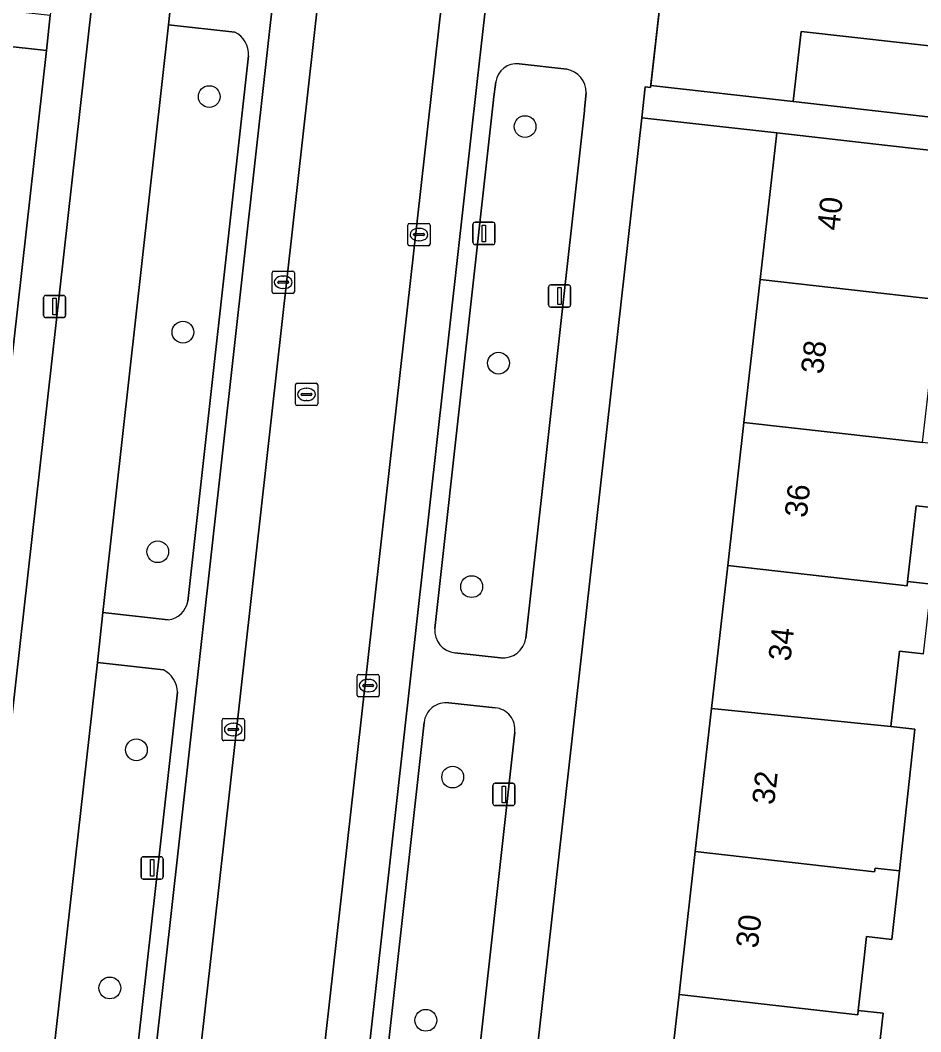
# Model space of a CAD drawing. Extents: x 162026 to 163502, y 387295 to 388169.
# Drawn here: x 162271.99 to 162312.4, y 387747.09 to 387792.48 of the extents above; entities that cross this region are included whole.
import ezdxf

# ---------------------------------------------------------------- set-up
doc = ezdxf.new("R2010")
doc.units = 0
for name, color, linetype in [('IMGEO_Berm_groen', 7, 'Continuous'), ('IMGEO_Boom', 7, 'Continuous'), ('IMGEO_Erf', 7, 'Continuous'), ('IMGEO_Fietspad_gesloten', 7, 'Continuous'), ('IMGEO_Groenvoorziening', 7, 'Continuous'), ('IMGEO_Kolk', 7, 'Continuous'), ('IMGEO_Lichtmast', 7, 'Continuous'), ('IMGEO_Muur', 7, 'Continuous'), ('IMGEO_Pand', 7, 'Continuous'), ('IMGEO_Pand_nummerreeks', 7, 'Continuous'), ('IMGEO_Parkeervlak_open', 7, 'Continuous'), ('IMGEO_Rijbaan_lokaal_gesloten', 7, 'Continuous'), ('IMGEO_Rioolput', 7, 'Continuous'), ('IMGEO_Voetpad_open', 7, 'Continuous')]:
    doc.layers.add(name, color=color, linetype=linetype)

msp = doc.modelspace()

# ---------------------------------------------------------------- linework, layer by layer
at = {"layer": 'IMGEO_Berm_groen'}
for points in [[(162281.616, 387791.948), (162278.652, 387792.276), (162275.701, 387765.902), (162278.634, 387765.568)], [(162279.508, 387766.397), (162282.229, 387790.883)], [(162278.414, 387763.326), (162275.454, 387763.658), (162272.106, 387733.912), (162274.927, 387733.596)], [(162275.919, 387734.426), (162279.054, 387762.323)]]:
    msp.add_lwpolyline(points, dxfattribs=at)
for centre, radius, start, end in [((162281.14, 387790.965), 1.092, 355.6719, 64.1764), ((162278.505, 387766.579), 1.019, 277.2498, 349.7229), ((162277.921, 387762.306), 1.133, 0.865, 64.2178)]:
    msp.add_arc(centre, radius, start, end, dxfattribs=at)
at = {"layer": 'IMGEO_Boom'}
for centre in [(162280.473, 387789.054), (162294.643, 387787.708), (162279.293, 387778.481), (162293.45, 387777.094), (162278.163, 387768.63), (162292.248, 387767.063), (162277.204, 387759.741), (162291.396, 387758.518), (162276.01, 387749.054), (162290.189, 387747.603)]:
    msp.add_circle(centre, 0.489, dxfattribs=at)
at = {"layer": 'IMGEO_Erf'}
for points in [[(162360.929, 387806.153), (162306.963, 387812.388), (162304.731, 387812.656), (162302.745, 387811.357), (162302.135, 387805.96), (162300.281, 387789.552), (162306.672, 387788.828), (162307.029, 387791.981), (162313.859, 387791.208)], [(162313.317, 387770.569), (162312.194, 387770.696), (162311.809, 387767.301), (162312.879, 387767.18)], [(162312.523, 387764.042), (162311.441, 387764.164), (162311.058, 387760.783), (162312.139, 387760.661), (162311.441, 387754.307), (162311.093, 387751.233), (162309.97, 387751.36), (162309.816, 387750), (162309.594, 387748.046), (162310.706, 387747.921), (162310.348, 387744.766)]]:
    msp.add_lwpolyline(points, dxfattribs=at)
for points in [[(162273.165, 387791.126), (162267.189, 387791.787), (162266.468, 387785.258), (162265.764, 387778.887), (162265.064, 387772.546), (162264.36, 387766.174), (162263.657, 387759.813), (162262.943, 387753.352), (162262.573, 387750), (162262.226, 387746.862), (162261.527, 387740.53), (162260.823, 387734.159), (162260.125, 387727.838), (162259.419, 387721.447), (162258.717, 387715.095), (162257.997, 387708.577), (162257.287, 387708.655), (162257.121, 387707.155), (162258.204, 387707.032), (162263.701, 387706.408), (162268.384, 387748.57)], [(162301.695, 387750), (162302.282, 387755.18), (162303.009, 387761.598), (162303.736, 387768.016), (162304.463, 387774.434), (162305.191, 387780.852), (162305.935, 387787.422), (162299.876, 387788.101), (162295.696, 387750.809), (162291.817, 387716.197), (162290.503, 387704.362), (162296.448, 387703.689), (162297.192, 387710.254), (162297.919, 387716.672), (162298.646, 387723.09), (162299.373, 387729.508), (162300.1, 387735.926), (162300.828, 387742.344), (162301.555, 387748.762)]]:
    msp.add_lwpolyline(points, close=True, dxfattribs=at)
at = {"layer": 'IMGEO_Fietspad_gesloten'}
for points in [[(162288.097, 387908.488), (162278.956, 387826.545), (162278.87, 387825.665), (162278.372, 387825.72), (162277.589, 387818.699), (162278.067, 387818.669), (162270.183, 387748.502), (162261.381, 387669.505)], [(162272.106, 387733.912), (162275.454, 387763.658), (162275.701, 387765.902), (162278.652, 387792.276), (162278.879, 387794.52), (162280.59, 387809.842), (162281.546, 387818.246), (162282.058, 387818.211), (162282.843, 387825.189), (162282.325, 387825.242), (162283.687, 387837.34), (162286.582, 387863.057), (162286.832, 387865.282)]]:
    msp.add_lwpolyline(points, dxfattribs=at)
at = {"layer": 'IMGEO_Groenvoorziening'}
for points in [[(162296.511, 387790.278), (162294.372, 387790.52)], [(162293.326, 387789.719), (162293.224, 387788.934), (162293.22, 387788.901), (162290.6, 387765.183)], [(162297.317, 387788.491), (162297.385, 387789.226)], [(162294.678, 387764.747), (162297.308, 387788.408), (162297.317, 387788.491)], [(162291.488, 387764.093), (162293.544, 387763.874)], [(162293.308, 387761.627), (162291.221, 387761.847)], [(162290.111, 387760.971), (162287.029, 387733.23)], [(162291.103, 387732.722), (162294.178, 387760.535)]]:
    msp.add_lwpolyline(points, dxfattribs=at)
for centre, radius, start, end in [((162294.258, 387789.586), 0.941, 83.025, 171.8629), ((162296.332, 387789.24), 1.053, 359.2191, 80.2204), ((162291.593, 387765.085), 0.998, 174.3766, 263.9614), ((162293.658, 387764.899), 1.031, 263.6367, 351.5444), ((162291.096, 387760.865), 0.99, 82.7249, 173.8353), ((162293.218, 387760.663), 0.968, 352.4014, 84.6875)]:
    msp.add_arc(centre, radius, start, end, dxfattribs=at)
at = {"layer": 'IMGEO_Kolk'}
for p, q in [((162289.458, 387783.362), (162290.31, 387783.362)), ((162289.383, 387782.436), (162289.383, 387783.288)), ((162289.685, 387782.905), (162290.083, 387782.905)), ((162289.871, 387783.142), (162289.896, 387783.142)), ((162290.384, 387783.288), (162290.384, 387782.436)), ((162289.642, 387782.856), (162289.642, 387782.868)), ((162290.08, 387782.819), (162289.682, 387782.819)), ((162289.894, 387782.582), (162289.869, 387782.582)), ((162290.126, 387782.868), (162290.126, 387782.856)), ((162290.31, 387782.362), (162289.458, 387782.362)), ((162283.293, 387780.296), (162283.293, 387781.148)), ((162283.368, 387781.222), (162284.22, 387781.222)), ((162284.294, 387781.148), (162284.294, 387780.296)), ((162283.552, 387780.716), (162283.552, 387780.728)), ((162283.99, 387780.679), (162283.592, 387780.679)), ((162283.595, 387780.765), (162283.993, 387780.765)), ((162283.781, 387781.002), (162283.806, 387781.002)), ((162284.036, 387780.728), (162284.036, 387780.716)), ((162284.22, 387780.222), (162283.368, 387780.222)), ((162283.804, 387780.442), (162283.779, 387780.442)), ((162287.103, 387762.197), (162287.103, 387763.049)), ((162287.178, 387763.123), (162288.03, 387763.123)), ((162288.104, 387763.049), (162288.104, 387762.197)), ((162287.362, 387762.617), (162287.362, 387762.629)), ((162287.8, 387762.58), (162287.402, 387762.58)), ((162287.405, 387762.666), (162287.803, 387762.666)), ((162287.591, 387762.903), (162287.616, 387762.903)), ((162287.846, 387762.629), (162287.846, 387762.617)), ((162288.03, 387762.123), (162287.178, 387762.123)), ((162287.614, 387762.343), (162287.589, 387762.343)), ((162281.126, 387761.152), (162281.978, 387761.152)), ((162281.051, 387760.226), (162281.051, 387761.078)), ((162281.31, 387760.646), (162281.31, 387760.658)), ((162281.353, 387760.695), (162281.751, 387760.695)), ((162281.539, 387760.932), (162281.564, 387760.932)), ((162281.794, 387760.658), (162281.794, 387760.646)), ((162282.052, 387761.078), (162282.052, 387760.226)), ((162281.748, 387760.609), (162281.35, 387760.609)), ((162281.562, 387760.372), (162281.537, 387760.372)), ((162281.978, 387760.152), (162281.126, 387760.152))]:
    msp.add_line(p, q, dxfattribs=at)
for points in [[(162289.458, 387783.362), (162290.31, 387783.362)], [(162289.383, 387782.436), (162289.383, 387783.288)], [(162290.384, 387783.288), (162290.384, 387782.436)], [(162290.31, 387782.362), (162289.458, 387782.362)], [(162283.293, 387780.296), (162283.293, 387781.148)], [(162283.368, 387781.222), (162284.22, 387781.222)], [(162284.294, 387781.148), (162284.294, 387780.296)], [(162284.22, 387780.222), (162283.368, 387780.222)], [(162287.103, 387762.197), (162287.103, 387763.049)], [(162287.178, 387763.123), (162288.03, 387763.123)], [(162288.104, 387763.049), (162288.104, 387762.197)], [(162288.03, 387762.123), (162287.178, 387762.123)], [(162281.126, 387761.152), (162281.978, 387761.152)], [(162281.051, 387760.226), (162281.051, 387761.078)], [(162282.052, 387761.078), (162282.052, 387760.226)], [(162281.978, 387760.152), (162281.126, 387760.152)]]:
    msp.add_lwpolyline(points, dxfattribs=at)
for centre, radius, start, end in [((162289.46, 387783.286), 0.0765, 91.552, 178.448), ((162289.46, 387783.286), 0.0765, 91.552, 178.448), ((162290.308, 387783.286), 0.0765, 1.552, 88.448), ((162290.308, 387783.286), 0.0765, 1.552, 88.448), ((162289.682, 387782.865), 0.0403, 85.8775, 175.7526), ((162290.087, 387782.867), 0.0386, 1.7309, 96.639), ((162289.679, 387782.855), 0.0366, 178.938, 274.7102), ((162290.083, 387782.862), 0.043, 264.8664, 352.4533), ((162289.46, 387782.438), 0.0765, 181.552, 268.448), ((162289.46, 387782.438), 0.0765, 181.552, 268.448), ((162290.308, 387782.438), 0.0765, 271.552, 358.448), ((162290.308, 387782.438), 0.0765, 271.552, 358.448), ((162283.37, 387781.146), 0.0765, 91.552, 178.448), ((162283.37, 387781.146), 0.0765, 91.552, 178.448), ((162284.218, 387781.146), 0.0765, 1.552, 88.448), ((162284.218, 387781.146), 0.0765, 1.552, 88.448), ((162283.592, 387780.725), 0.0403, 85.8775, 175.7526), ((162283.589, 387780.715), 0.0366, 178.938, 274.7102), ((162283.993, 387780.722), 0.043, 264.8664, 352.4533), ((162283.997, 387780.727), 0.0386, 1.7309, 96.639), ((162283.37, 387780.298), 0.0765, 181.552, 268.448), ((162283.37, 387780.298), 0.0765, 181.552, 268.448), ((162284.218, 387780.298), 0.0765, 271.552, 358.448), ((162284.218, 387780.298), 0.0765, 271.552, 358.448), ((162287.18, 387763.047), 0.0765, 91.552, 178.448), ((162287.18, 387763.047), 0.0765, 91.552, 178.448), ((162288.028, 387763.047), 0.0765, 1.552, 88.448), ((162288.028, 387763.047), 0.0765, 1.552, 88.448), ((162287.402, 387762.626), 0.0403, 85.8775, 175.7526), ((162287.399, 387762.616), 0.0366, 178.938, 274.7102), ((162287.803, 387762.623), 0.043, 264.8664, 352.4533), ((162287.807, 387762.628), 0.0386, 1.7309, 96.639), ((162287.18, 387762.199), 0.0765, 181.552, 268.448), ((162287.18, 387762.199), 0.0765, 181.552, 268.448), ((162288.028, 387762.199), 0.0765, 271.552, 358.448), ((162288.028, 387762.199), 0.0765, 271.552, 358.448), ((162281.128, 387761.076), 0.0765, 91.552, 178.448), ((162281.128, 387761.076), 0.0765, 91.552, 178.448), ((162281.976, 387761.076), 0.0765, 1.552, 88.448), ((162281.976, 387761.076), 0.0765, 1.552, 88.448), ((162281.35, 387760.655), 0.0403, 85.8775, 175.7526), ((162281.755, 387760.657), 0.0386, 1.7309, 96.639), ((162281.128, 387760.228), 0.0765, 181.552, 268.448), ((162281.128, 387760.228), 0.0765, 181.552, 268.448), ((162281.347, 387760.645), 0.0366, 178.938, 274.7102), ((162281.751, 387760.652), 0.043, 264.8664, 352.4533), ((162281.976, 387760.228), 0.0765, 271.552, 358.448), ((162281.976, 387760.228), 0.0765, 271.552, 358.448)]:
    msp.add_arc(centre, radius, start, end, dxfattribs=at)
for centre, major_axis, ratio, start_param, end_param in [((162289.87, 387782.862), (-0.387, 0.002), 0.722429, 4.712389, 7.853982), ((162289.895, 387782.862), (-0.39, 0.002), 0.717154, 1.570796, 4.712389), ((162283.78, 387780.722), (-0.387, 0.002), 0.722429, 4.712389, 7.853982), ((162283.805, 387780.722), (-0.39, 0.002), 0.717154, 1.570796, 4.712389), ((162287.59, 387762.623), (-0.387, 0.002), 0.722429, 4.712389, 7.853982), ((162287.615, 387762.623), (-0.39, 0.002), 0.717154, 1.570796, 4.712389), ((162281.538, 387760.652), (-0.387, 0.002), 0.722429, 4.712389, 7.853982), ((162281.563, 387760.652), (-0.39, 0.002), 0.717154, 1.570796, 4.712389)]:
    msp.add_ellipse(centre, major_axis=major_axis, ratio=ratio, start_param=start_param, end_param=end_param, dxfattribs=at)
at = {"layer": 'IMGEO_Lichtmast'}
for p, q in [((162292.404, 387783.414), (162293.194, 387783.414)), ((162293.194, 387783.414), (162292.404, 387783.414)), ((162292.304, 387782.514), (162292.304, 387783.314)), ((162292.304, 387783.314), (162292.304, 387782.514)), ((162293.294, 387783.314), (162293.294, 387782.514)), ((162293.294, 387782.514), (162293.294, 387783.314)), ((162293.194, 387782.414), (162292.404, 387782.414)), ((162292.404, 387782.414), (162293.194, 387782.414)), ((162295.696, 387779.705), (162295.696, 387780.505)), ((162295.696, 387780.505), (162295.696, 387779.705)), ((162295.796, 387780.605), (162296.586, 387780.605)), ((162296.586, 387780.605), (162295.796, 387780.605)), ((162296.686, 387780.505), (162296.686, 387779.705)), ((162296.686, 387779.705), (162296.686, 387780.505)), ((162273.038, 387779.234), (162273.038, 387780.034)), ((162273.038, 387780.034), (162273.038, 387779.234)), ((162273.138, 387780.134), (162273.928, 387780.134)), ((162273.928, 387780.134), (162273.138, 387780.134)), ((162274.028, 387780.034), (162274.028, 387779.234)), ((162274.028, 387779.234), (162274.028, 387780.034)), ((162296.586, 387779.605), (162295.796, 387779.605)), ((162295.796, 387779.605), (162296.586, 387779.605)), ((162273.928, 387779.134), (162273.138, 387779.134)), ((162273.138, 387779.134), (162273.928, 387779.134)), ((162293.201, 387757.338), (162293.201, 387758.138)), ((162293.201, 387758.138), (162293.201, 387757.338)), ((162293.301, 387758.238), (162294.091, 387758.238)), ((162294.091, 387758.238), (162293.301, 387758.238)), ((162294.191, 387758.138), (162294.191, 387757.338)), ((162294.191, 387757.338), (162294.191, 387758.138)), ((162294.091, 387757.238), (162293.301, 387757.238)), ((162293.301, 387757.238), (162294.091, 387757.238)), ((162277.414, 387754.042), (162277.414, 387754.842)), ((162277.414, 387754.842), (162277.414, 387754.042)), ((162277.514, 387754.942), (162278.304, 387754.942)), ((162278.304, 387754.942), (162277.514, 387754.942)), ((162278.404, 387754.842), (162278.404, 387754.042)), ((162278.404, 387754.042), (162278.404, 387754.842)), ((162278.304, 387753.942), (162277.514, 387753.942)), ((162277.514, 387753.942), (162278.304, 387753.942))]:
    msp.add_line(p, q, dxfattribs=at)
for points in [[(162292.724, 387783.289), (162292.874, 387783.289), (162292.874, 387782.539), (162292.724, 387782.539), (162292.724, 387783.289)], [(162296.116, 387780.48), (162296.266, 387780.48), (162296.266, 387779.73), (162296.116, 387779.73), (162296.116, 387780.48)], [(162273.458, 387780.009), (162273.608, 387780.009), (162273.608, 387779.259), (162273.458, 387779.259), (162273.458, 387780.009)], [(162293.621, 387758.113), (162293.771, 387758.113), (162293.771, 387757.363), (162293.621, 387757.363), (162293.621, 387758.113)], [(162277.834, 387754.817), (162277.984, 387754.817), (162277.984, 387754.067), (162277.834, 387754.067), (162277.834, 387754.817)]]:
    msp.add_lwpolyline(points, dxfattribs=at)
for centre, start, end in [((162292.404, 387783.314), 90, 180), ((162292.404, 387783.314), 90, 180), ((162293.194, 387783.314), 0, 90), ((162293.194, 387783.314), 360, 90), ((162292.404, 387782.514), 180, 270), ((162292.404, 387782.514), 180, 270), ((162293.194, 387782.514), 270, 0), ((162293.194, 387782.514), 270, 0), ((162295.796, 387780.505), 90, 180), ((162295.796, 387780.505), 90, 180), ((162296.586, 387780.505), 0, 90), ((162296.586, 387780.505), 360, 90), ((162273.138, 387780.034), 90, 180), ((162273.138, 387780.034), 90, 180), ((162273.928, 387780.034), 0, 90), ((162273.928, 387780.034), 360, 90), ((162295.796, 387779.705), 180, 270), ((162295.796, 387779.705), 180, 270), ((162296.586, 387779.705), 270, 0), ((162296.586, 387779.705), 270, 0), ((162273.138, 387779.234), 180, 270), ((162273.138, 387779.234), 180, 270), ((162273.928, 387779.234), 270, 0), ((162273.928, 387779.234), 270, 0), ((162293.301, 387758.138), 90, 180), ((162293.301, 387758.138), 90, 180), ((162294.091, 387758.138), 0, 90), ((162294.091, 387758.138), 360, 90), ((162293.301, 387757.338), 180, 270), ((162293.301, 387757.338), 180, 270), ((162294.091, 387757.338), 270, 0), ((162294.091, 387757.338), 270, 0), ((162277.514, 387754.842), 90, 180), ((162277.514, 387754.842), 90, 180), ((162278.304, 387754.842), 0, 90), ((162278.304, 387754.842), 360, 90), ((162277.514, 387754.042), 180, 270), ((162277.514, 387754.042), 180, 270), ((162278.304, 387754.042), 270, 0), ((162278.304, 387754.042), 270, 0)]:
    msp.add_arc(centre, 0.1, start, end, dxfattribs=at)
at = {"layer": 'IMGEO_Muur'}
msp.add_lwpolyline([(162300.27, 387789.459), (162302.135, 387805.96)], dxfattribs=at)
at = {"layer": 'IMGEO_Pand'}
for points in [[(162313.859, 387791.208), (162307.029, 387791.981), (162306.672, 387788.828), (162313.502, 387788.054)], [(162313.259, 387779.939), (162313.285, 387780.167), (162313.666, 387783.538), (162314.692, 387783.422), (162315.029, 387786.391), (162310.904, 387786.859), (162305.935, 387787.422), (162305.191, 387780.852)], [(162305.191, 387780.852), (162304.463, 387774.434), (162312.475, 387773.527), (162312.873, 387777.035), (162314.026, 387776.904), (162314.382, 387780.043), (162313.285, 387780.167), (162313.259, 387779.939)], [(162311.787, 387767.105), (162311.809, 387767.301), (162312.194, 387770.696), (162313.317, 387770.569), (162313.636, 387773.384), (162312.475, 387773.527), (162304.463, 387774.434), (162303.736, 387768.016)], [(162303.736, 387768.016), (162303.009, 387761.598), (162311.058, 387760.783), (162311.441, 387764.164), (162312.523, 387764.042), (162312.879, 387767.18), (162311.809, 387767.301), (162311.787, 387767.105)], [(162312.139, 387760.661), (162311.058, 387760.783), (162303.009, 387761.598), (162302.282, 387755.18), (162310.329, 387754.269), (162310.347, 387754.431), (162311.441, 387754.307)], [(162309.572, 387747.854), (162309.594, 387748.046), (162309.816, 387750), (162309.97, 387751.36), (162311.093, 387751.233), (162311.441, 387754.307), (162310.347, 387754.431), (162310.329, 387754.269), (162302.282, 387755.18), (162301.695, 387750), (162301.555, 387748.762)], [(162301.555, 387748.762), (162300.828, 387742.344), (162308.92, 387741.428), (162309.984, 387741.4), (162311.513, 387741.226), (162311.895, 387744.592), (162310.348, 387744.766), (162310.706, 387747.921), (162309.594, 387748.046), (162309.572, 387747.854)]]:
    msp.add_lwpolyline(points, close=True, dxfattribs=at)
at = {"layer": 'IMGEO_Parkeervlak_open'}
for points in [[(162280.695, 387751.699), (162287.006, 387808.114)], [(162284.902, 387807.407), (162278.703, 387751.857), (162273.411, 387704.935), (162275.389, 387704.712), (162277.051, 387719.431), (162280.695, 387751.699)], [(162292.493, 387807.458), (162285.406, 387744.3), (162281.03, 387705.382)], [(162283.154, 387706.135), (162287.384, 387743.942), (162292.495, 387789.737), (162292.997, 387794.228), (162294.36, 387806.319)]]:
    msp.add_lwpolyline(points, dxfattribs=at)
at = {"layer": 'IMGEO_Rijbaan_lokaal_gesloten'}
for points in [[(162293.541, 387866.933), (162293.019, 387862.21), (162290.172, 387836.436), (162289.313, 387828.914), (162289.192, 387827.743), (162287.762, 387814.78), (162287.006, 387808.114), (162280.695, 387751.699), (162277.051, 387719.431)], [(162285.406, 387744.3), (162292.493, 387807.458), (162292.904, 387811.196), (162294.998, 387829.811), (162295.007, 387829.89), (162295.154, 387831.121), (162295.688, 387835.856), (162298.53, 387861.44), (162299.054, 387866.158)]]:
    msp.add_lwpolyline(points, dxfattribs=at)
at = {"layer": 'IMGEO_Rioolput'}
for p, q in [((162284.339, 387775.263), (162284.339, 387776.115)), ((162284.414, 387776.189), (162285.266, 387776.189)), ((162285.34, 387776.115), (162285.34, 387775.263)), ((162284.598, 387775.683), (162284.598, 387775.695)), ((162285.036, 387775.646), (162284.638, 387775.646)), ((162284.641, 387775.732), (162285.039, 387775.732)), ((162284.827, 387775.969), (162284.852, 387775.969)), ((162285.082, 387775.695), (162285.082, 387775.683)), ((162285.266, 387775.189), (162284.414, 387775.189)), ((162284.85, 387775.409), (162284.825, 387775.409))]:
    msp.add_line(p, q, dxfattribs=at)
for points in [[(162284.339, 387775.263), (162284.339, 387776.115)], [(162284.414, 387776.189), (162285.266, 387776.189)], [(162285.34, 387776.115), (162285.34, 387775.263)], [(162285.266, 387775.189), (162284.414, 387775.189)]]:
    msp.add_lwpolyline(points, dxfattribs=at)
for centre, radius, start, end in [((162284.416, 387776.113), 0.0765, 91.552, 178.448), ((162284.416, 387776.113), 0.0765, 91.552, 178.448), ((162285.264, 387776.113), 0.0765, 1.552, 88.448), ((162285.264, 387776.113), 0.0765, 1.552, 88.448), ((162284.638, 387775.692), 0.0403, 85.8775, 175.7526), ((162284.635, 387775.682), 0.0366, 178.938, 274.7102), ((162285.039, 387775.689), 0.043, 264.8664, 352.4533), ((162285.043, 387775.694), 0.0386, 1.7309, 96.639), ((162284.416, 387775.265), 0.0765, 181.552, 268.448), ((162284.416, 387775.265), 0.0765, 181.552, 268.448), ((162285.264, 387775.265), 0.0765, 271.552, 358.448), ((162285.264, 387775.265), 0.0765, 271.552, 358.448)]:
    msp.add_arc(centre, radius, start, end, dxfattribs=at)
for centre, major_axis, ratio, start_param, end_param in [((162284.826, 387775.689), (-0.387, 0.002), 0.722429, 4.712389, 7.853982), ((162284.851, 387775.689), (-0.39, 0.002), 0.717154, 1.570796, 4.712389)]:
    msp.add_ellipse(centre, major_axis=major_axis, ratio=ratio, start_param=start_param, end_param=end_param, dxfattribs=at)
at = {"layer": 'IMGEO_Voetpad_open'}
for points in [[(162278.638, 387840.188), (162277.973, 387834.139), (162277.255, 387827.421), (162277.144, 387825.832), (162276.387, 387818.853), (162275.948, 387815.9), (162273.341, 387792.696), (162273.165, 387791.126), (162268.384, 387748.57), (162263.701, 387706.408), (162263.602, 387705.513), (162260.688, 387679.28), (162259.835, 387671.845), (162259.358, 387667.311)], [(162258.548, 387665.971), (162258.434, 387664.862), (162260.283, 387664.663), (162260.87, 387664.615), (162261.381, 387669.505), (162270.183, 387748.502), (162278.067, 387818.669), (162277.589, 387818.699), (162278.372, 387825.72)], [(162290.361, 387703.086), (162290.503, 387704.362), (162291.817, 387716.197), (162295.696, 387750.809), (162299.876, 387788.101), (162300.031, 387789.486), (162300.27, 387789.459), (162300.281, 387789.552), (162302.135, 387805.96), (162302.745, 387811.357), (162303.178, 387815.842), (162302.483, 387815.921), (162299.685, 387816.236)], [(162273.411, 387704.935), (162278.703, 387751.857), (162284.902, 387807.407)], [(162294.36, 387806.319), (162292.997, 387794.228), (162292.495, 387789.737), (162287.384, 387743.942), (162283.154, 387706.135)], [(162281.83, 387794.192), (162278.879, 387794.52), (162278.652, 387792.276), (162281.616, 387791.948)], [(162282.229, 387790.883), (162279.508, 387766.397)], [(162294.372, 387790.52), (162296.511, 387790.278)], [(162290.6, 387765.183), (162293.22, 387788.901), (162293.224, 387788.934), (162293.326, 387789.719)], [(162313.502, 387788.054), (162306.672, 387788.828), (162300.281, 387789.552), (162300.27, 387789.459), (162300.031, 387789.486), (162299.876, 387788.101), (162305.935, 387787.422), (162310.904, 387786.859), (162315.029, 387786.391)], [(162297.385, 387789.226), (162297.317, 387788.491), (162297.308, 387788.408), (162294.678, 387764.747)], [(162278.634, 387765.568), (162275.701, 387765.902), (162275.454, 387763.658), (162278.414, 387763.326)], [(162293.544, 387763.874), (162291.488, 387764.093)], [(162279.054, 387762.323), (162275.919, 387734.426)], [(162291.221, 387761.847), (162293.308, 387761.627)], [(162287.029, 387733.23), (162290.111, 387760.971)], [(162294.178, 387760.535), (162291.103, 387732.722)]]:
    msp.add_lwpolyline(points, dxfattribs=at)
msp.add_lwpolyline([(162242.578, 387796.117), (162242.378, 387794.629), (162247.348, 387794.074), (162248.361, 387793.961), (162258.402, 387792.758), (162262.22, 387792.336), (162267.189, 387791.787), (162273.165, 387791.126), (162273.341, 387792.696)], close=True, dxfattribs=at)
for centre, radius, start, end in [((162281.14, 387790.965), 1.092, 355.6719, 64.1764), ((162294.258, 387789.586), 0.941, 83.025, 171.8629), ((162296.332, 387789.24), 1.053, 359.2191, 80.2204), ((162278.505, 387766.579), 1.019, 277.2498, 349.7229), ((162291.593, 387765.085), 0.998, 174.3766, 263.9614), ((162293.658, 387764.899), 1.031, 263.6367, 351.5444), ((162277.921, 387762.306), 1.133, 0.865, 64.2178), ((162291.096, 387760.865), 0.99, 82.7249, 173.8353), ((162293.218, 387760.663), 0.968, 352.4014, 84.6875)]:
    msp.add_arc(centre, radius, start, end, dxfattribs=at)

# ---------------------------------------------------------------- texts
at = {"layer": 'IMGEO_Pand_nummerreeks'}
for s, rotation, p in [('40', 83.5359, (162308.737, 387783.014)), ('38', 83.5359, (162308.007, 387776.573)), ('36', 83.5359, (162307.277, 387770.129)), ('34', 83.5359, (162306.547, 387763.688)), ('32', 83.5372, (162305.817, 387757.244)), ('30', 83.5359, (162305.088, 387750.809))]:
    msp.add_text(s, height=1, rotation=rotation, dxfattribs=at).set_placement(p)

doc.saveas('drawing.dxf')
